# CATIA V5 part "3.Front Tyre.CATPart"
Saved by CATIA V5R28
Part number: Front tyre
Bounding box of the stored display mesh (mm): x -44.5 to 44.5, y -196 to 196, z -196 to 196
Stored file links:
  D:\Catia Cycle design\3.Front Tyre.CATPart
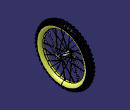
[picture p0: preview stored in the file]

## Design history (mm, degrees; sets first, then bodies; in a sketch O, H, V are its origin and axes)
Set1
  Sketch1 on zx-plane, origin (0, 0, 0), H (-1, 0, 0), V (0, 0, 1)
    construction line L1 (0, 0) -> (0, 170)
    arc A1 centre (0, 170) radius 22 from (22, 170) to (-22, 170) ccw
    point P2 (-22, 170)
    point P3 (22, 170)
    arc A2 centre (-23, 170) radius 1 from (-22, 170) to (-24, 170) ccw
    point P4 (-23, 170)
    point P5 (-24, 170)
    axis line L2 (22, 170) -> (-22, 170)
    point P6 (24, 170)
    point P7 (22, 170)
    arc A3 centre (23, 170) radius 1 from (22, 170) to (24, 170) cw
    arc A4 centre (0, 170) radius 24 from (-24, 170) to (-6.8557, 147) ccw
    point P9 (-24, 170)
    line L3 (-6.8557, 147) -> (6.8557, 147)
    point P11 (6.8557, 147)
    arc A5 centre (0, 170) radius 24 from (6.8557, 147) to (24, 170) ccw
    length L1 = 170
    radius A1 = 22
    radius A2 = 1
    distance L2 L3 = 23
    vertical: L1 V
    tangency: A2 A1, A4 A3, A4 A2, A3 A1
    horizontal: L2 H, L3 H
    coincidence: P5 L2, P4 L2, P9 L2, P11 A4, A4 A5, P3 P7, P5 P9
    symmetry: P5 P6 L1, P2 P7 L1, A2 A3 L1
  Plane1: type Offset, RefPlane xy-plane, Offset 149
  Plane2: type Offset, RefPlane zx-plane, Offset 149
  Point1: type Center, Curve Sketch7
  Point2: (34.5, -14.6239, 3.3378)
  Line1: type PtDir, RefPoint Point2, Direction (1, 0, 0), Start 0, End 8
  Line2: type PtPt, FirstPoint Point1, SecondPoint Point2
  Corner1: Element1 Line2, Element2 Line1, Radius 3
  Point3: type Center, Curve Sketch8
  Point4: (-34.5, 6.5083, 13.5145)
  Line3: type PtDir, RefPoint Point4, Direction (1, 0, 0), Start 0, End 8
  Line4: type PtPt, FirstPoint Point4, SecondPoint Point3
  Corner2: Element1 Line4, Element2 Line3, Radius 3
  Plane3: type Offset, RefPlane xy-plane, Offset 197
Body1 (main body)
  Shaft1: profile Sketch1, axis X axis, angle 360
  Sketch2 on yz-plane, origin (0, 0, 0), H (0, 1, 0), V (0, 0, 1)
    circle A1 centre (0, 0) radius 8.8
    circle A2 centre (0, 0) radius 5
    radius A1 = 8.8
    radius A2 = 5
  Pad1: profile Sketch2, direction (1, 0, 0), length 38.5, mirrored extent
  Sketch3 on start face of Pad1, origin (-38.5, 0, 0), H (0, -1, 0), V (0, 0, 1)
    circle A1 centre (0, 0) radius 11.5
    projected circle E1 centre (0, 0) radius 8.8 from edge [start face of Pad1 | face of Pad1 from Sketch2.A1]
    radius A1 = 11.5
  Pad2: profile Sketch3, direction (1, 0, 0), length 4
  Sketch4 on end face of Pad2, origin (-34.5, 0, 0), H (0, 1, 0), V (0, 0, 1)
    circle A1 centre (0, 0) radius 10
    radius A1 = 10
  Pad3: profile Sketch4, direction (1, 0, 0), length 4
  Mirror1: of the body so far, about yz-plane
  Fillet1: radius 1, on edge [face of Mirror1 | face of Mirror1]
  Fillet2: radius 1, on edge [end face of Pad2 | face of Pad3 from Sketch4.A1]
  Sketch5 on face of Mirror1, origin (30.5, 0, 0), H (0, -1, 0), V (0, 0, 1)
    circle A1 centre (0, 0) radius 19
    point P1 (0, 0)
    projected circle E1 centre (0, 0) radius 8.8 from edge [face of Mirror1 | face of Mirror1]
    radius A1 = 19
    coincidence: P1 H, P1 O
  Pad4: profile Sketch5, direction (-1, 0, 0), length 3
  Sketch6 on start face of Pad4, origin (30.5, 0, 0), H (0, 1, 0), V (0, 0, 1)
    circle A1 centre (0, 15) radius 1.5
    point P1 (0, 15)
    radius A1 = 1.5
    distance H P1 = 15
    coincidence: P1 V
  Pocket1: profile Sketch6, direction (-1, 0, 0), through (limit type 3)
  CircPattern1: of Pocket1, instances 14, angular step 25.7143 {= 360.0*1 deg/CircPattern1.AngularNumber}, axis from X axis
  Mirror2: of the body so far, about yz-plane
  Sketch7 on Plane1, origin (0, 0, 149), H (1, 0, 0), V (0, 1, 0)
    circle A1 centre (0, 0) radius 1.5
    point P1 (1.5, 0)
    radius A1 = 1.5
    coincidence: A1 P1, P1 H
  Pocket2: profile Sketch7, direction (0, 0, -1), length 5
  Rib1: profile Sketch7, centre curve Corner1
  CircPattern2: of Pocket2, instances 28, angular step 12.8571 {= 360.0*1 deg/CircPattern2.AngularNumber}, axis from X axis
  CircPattern3: of Rib1, instances 14, angular step 25.7143 {= 360.0*1 deg/CircPattern3.AngularNumber}, axis from X axis
  Sketch8 on Plane2, origin (0, 149, 0), H (-1, 0, 0), V (0, 0, 1)
    projected circle E1 centre (0, 0) radius 1.5 from edge [face of CircPattern2 | face of Mirror2]
  Rib2: profile Sketch8, centre curve Corner2
  CircPattern4: of Rib2, instances 14, angular step 25.7143 {= 360.0*1 deg/CircPattern4.AngularNumber}, axis from X axis
  Sketch9 on face of Mirror2, origin (38.5, 0, 0), H (0, 1, 0), V (0, 0, 1)
    circle A1 centre (0, 0) radius 7
    projected circle E1 centre (0, 0) radius 5 from edge [face of Mirror2 | face of Mirror2]
    radius A1 = 7
  Pad5: profile Sketch9, direction (1, 0, 0), length 6
  Sketch10 on Plane3, origin (0, 0, 197), H (1, 0, 0), V (0, 1, 0)
    point P1 (-4, 0)
    line L1 (-4, 0) -> (4, 0)
    line L2 (4, 0) -> (4, 12)
    line L3 (4, 12) -> (-4, 12)
    line L4 (-4, 12) -> (-4, 0)
    point P5 (-16, 6)
    line L5 (-16, 6) -> (-16, -6)
    point P6 (-16, -6)
    line L6 (-16, -6) -> (-10, -3)
    point P7 (-10, -3)
    line L7 (-10, -3) -> (-10, 3)
    point P8 (-10, 3)
    line L8 (-10, 3) -> (-16, 6)
    reference projected point E1 (0, 0) from edge
    point P9 (16, -6)
    point P10 (16, 6)
    line L9 (16, 6) -> (16, -6)
    point P11 (10, 3)
    line L10 (10, 3) -> (16, 6)
    point P12 (10, -3)
    line L11 (10, -3) -> (10, 3)
    line L12 (16, -6) -> (10, -3)
    distance L4 L2 = 8
    distance L3 L1 = 12
    length L5 = 12
    length L7 = 6
    distance L5 L7 = 6
    distance E1 L7 = 10
    coincidence: P1 H
    horizontal: L1 H, L3 H
    vertical: L2 V, L4 V, L5 V, L7 V
    symmetry: L4 L2 V, P7 P8 H, P6 P5 H, P6 P9 V, P5 P10 V, L5 L9 V, P8 P11 V, L8 L10 V, P7 P12 V, L7 L11 V, L6 L12 V
  Pad6: profile Sketch10, direction (0, 0, 1), up to the existing solid (limit type 2)
  CircPattern5: of Pad6, instances 50, angular step 7.2, axis from X axis
  Sketch11 on zx-plane, origin (0, 0, 0), H (-1, 0, 0), V (0, 0, 1)
    arc A1 centre (0, 171) radius 25 from (25, 171) to (-24.9983, 170.7064) ccw
    point P1 (0, 171)
    reference projected line E1 (-4, 197) -> (4, 197) from edge [face of Pad6 from Sketch10.L3 | start face of Pad6]
    line L1 (-24.9983, 170.7064) -> (-25.5629, 218.7841)
    line L2 (-25.5629, 218.7841) -> (25, 218.7841)
    line L3 (25, 218.7841) -> (25, 171)
    radius A1 = 25
    distance A1 E1 = 1
    coincidence: P1 V
    tangency: L1 A1
    horizontal: L2 H
    vertical: L3 V
  Groove1: profile Sketch11, axis X axis, angle 360
  Mirror3: of Pad5, about yz-plane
